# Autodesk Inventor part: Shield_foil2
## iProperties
Shininess: 64.0
Length Units: 11269
Angle Units: 11279
Time Units: 11290
Mass Units: 11283
Length Display Precision: 3
Angle Display Precision: 2
Compacted: True
Part Number: Shield_foil2
Document SubType Name: Modeling
Created: 2003-02
Material: Standard
Designer: hofer_a
Density: 0.0
Volumn: 0.0
Area: 0.0
PropertySet Name: Model Information
Control State: 0
Master: False
Checked Out: False
Author: hofer_a
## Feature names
1. Extrusion1
